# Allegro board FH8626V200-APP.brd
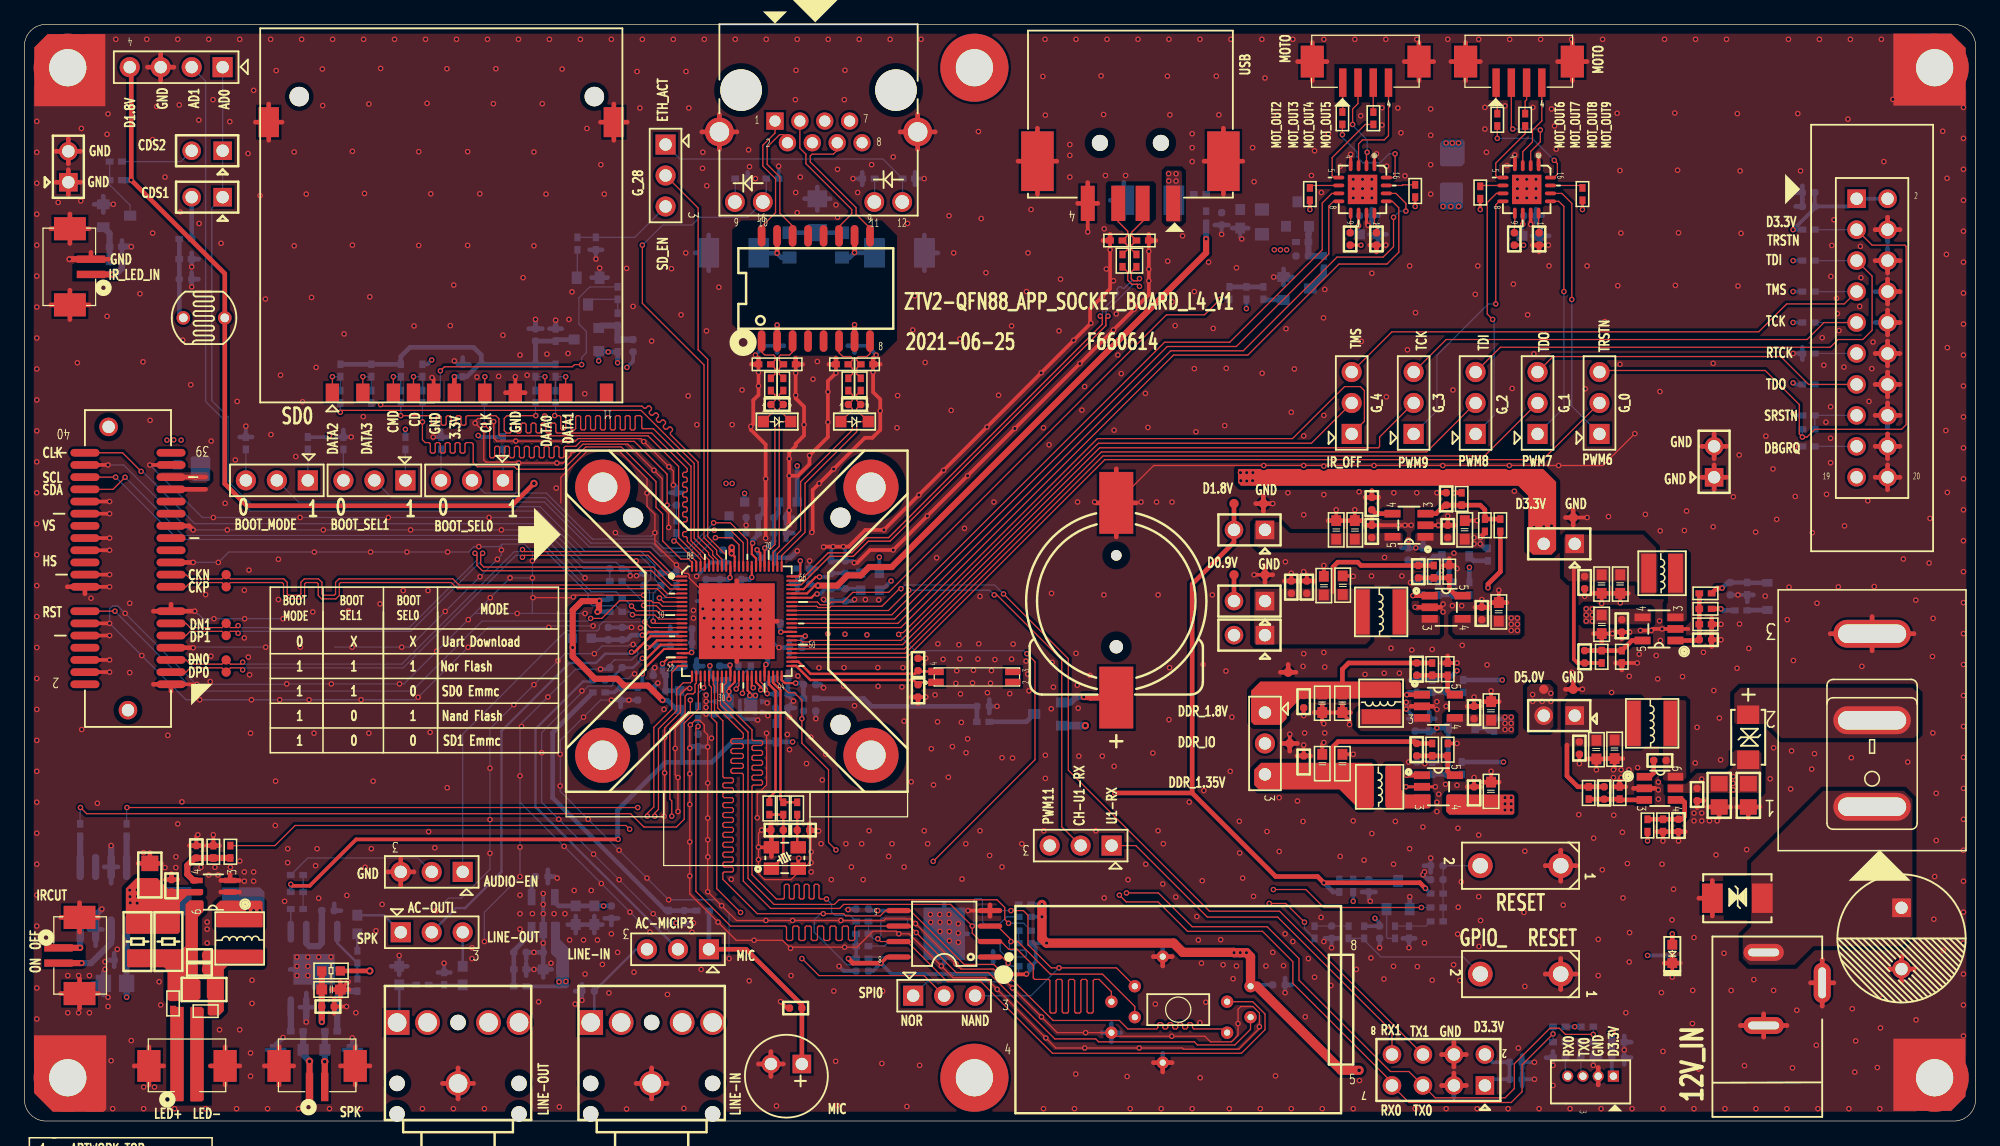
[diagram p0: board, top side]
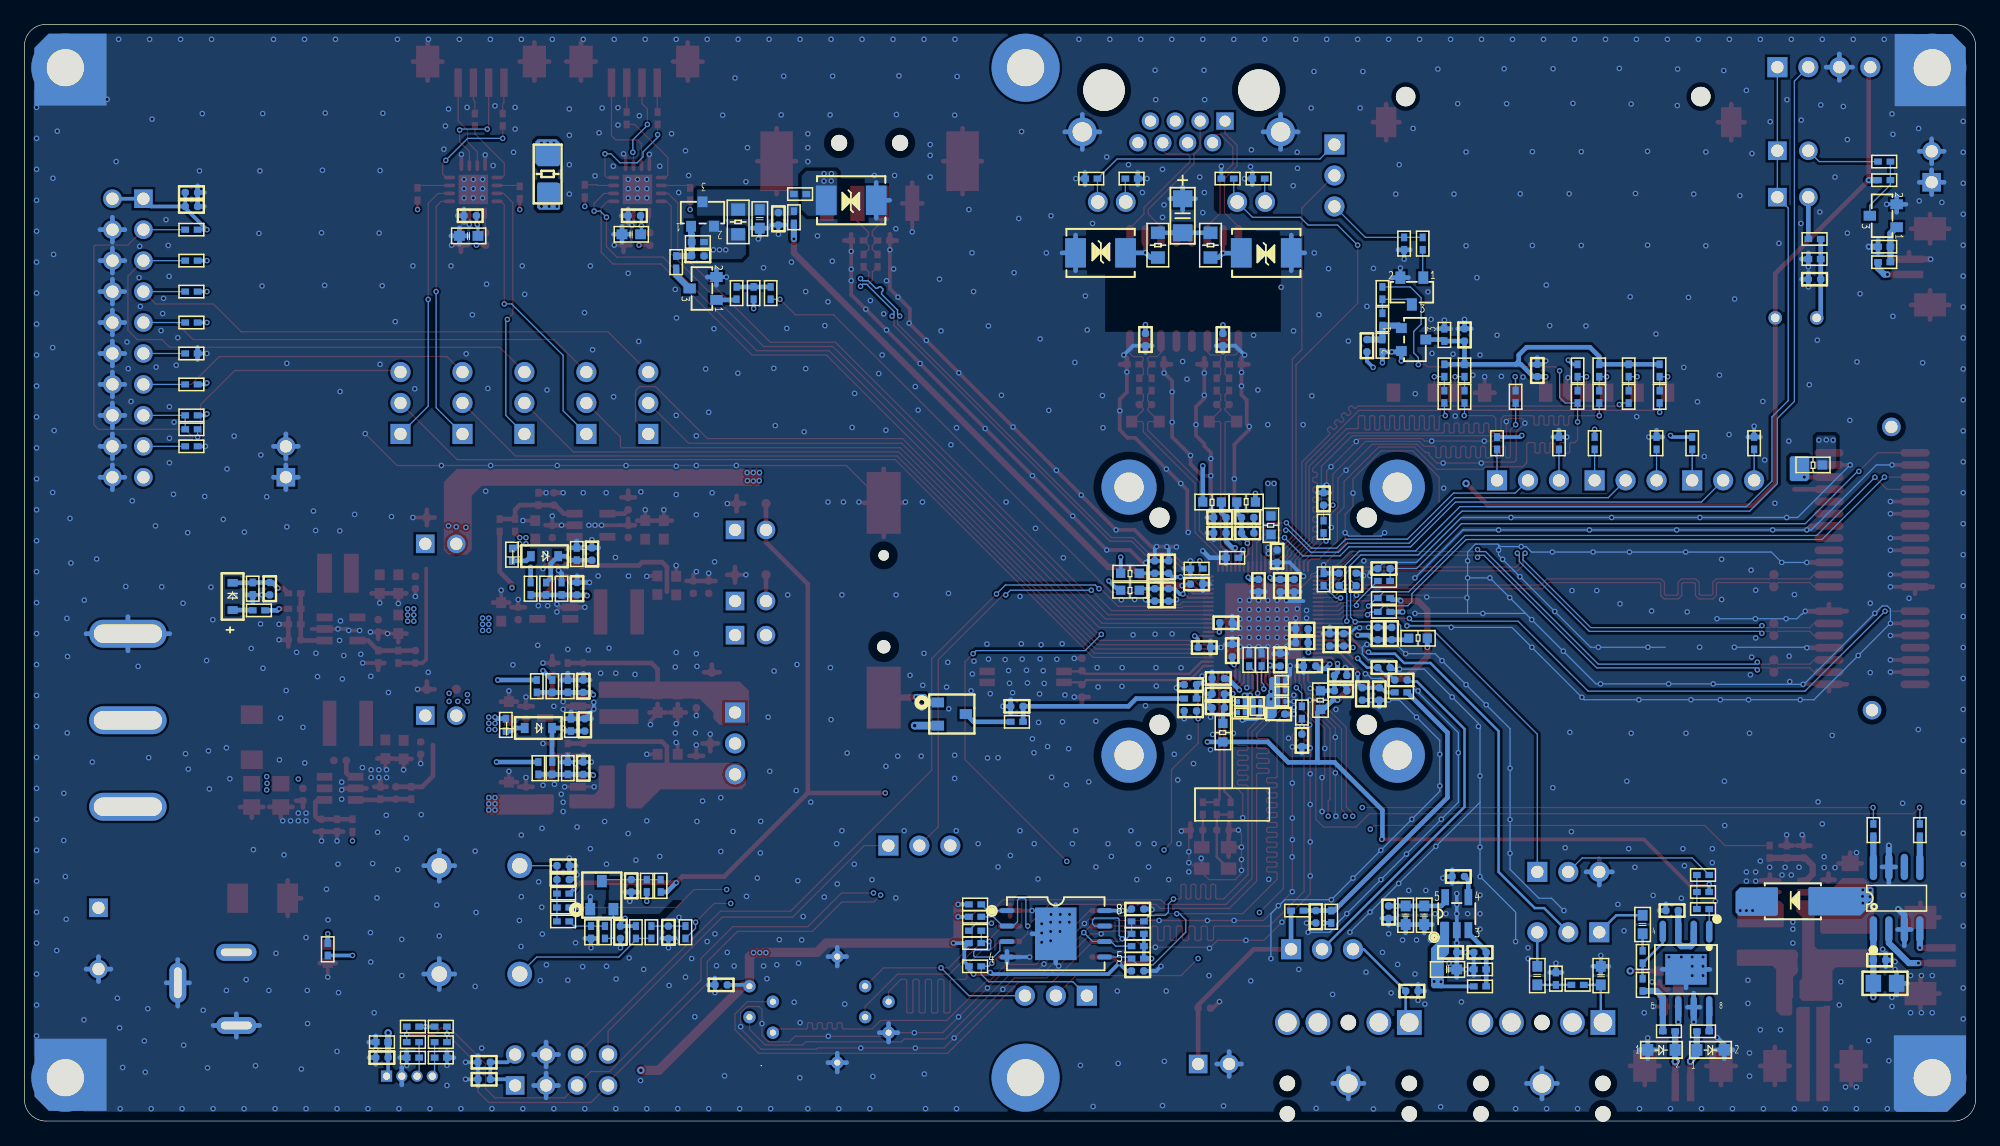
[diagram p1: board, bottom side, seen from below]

Outline 160 x 90 mm; copper layers: TOP, GND, VCC, BOTTOM. Coordinates in mm from the lower left corner of the outline.
Outline path: 0,88.22 arc(0.52,89.48) 1.78,90 158.22,90 arc(159.48,89.48) 160,88.22 160,1.78 arc(159.48,0.52) 158.22,0 1.78,0 arc(0.52,0.52) 0,1.78 0,88.22

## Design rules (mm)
net group ARM_JTAG_TRSTN: nets ARM_JTAG_TRSTN JTAG_SRSTN
net group CDS1: nets CDS1 N00509
net group CIS_CLK: nets CIS_CLK N16786493
net group DDR_D1.8V: nets DDR_D1.8V N15061
net group EN2: nets EN2 N11558
net group EN3: nets EN3 N17828
net group GPIO_RESET: nets GPIO_RESET N06017
net group IR_LED_IN: nets IR_LED_IN N12968
net group MOTO_OUT_2: nets MOTO_OUT_2 N16674187
net group MOTO_OUT_4: nets MOTO_OUT_4 N16674222
net group MOTO_OUT_6: nets MOTO_OUT_6 N16674257
net group MOTO_OUT_8: nets MOTO_OUT_8 N16674292
net group SPI1: nets NOR_CS SPI0_CSN_0
net group USB_PWREN: nets N08717 USB_PWREN
net group USBN: nets USB_DM USBN
net group USBP: nets USB_DP USBP
net group CDS2: nets CDS2 CIS_SCL CIS_SDA N07170 N13141 N16750268 N16750308 N16751673 N16786550 N16786676 N16794051 N16800878
net group CLK_IN: nets CLK_IN CLK_OUT N16795922 N16795926
net group EN1: nets EN1 N15235 N20335
net group EPHY_RXN: nets N16425817
net group EPHY_RXP: nets N16425841
net group EPHY_TXN: nets N16425857
net group EPHY_TXP: nets N16425869
net group HOLD: nets HOLD
net group LAN: nets EPHY_RXN EPHY_RXP EPHY_TXN EPHY_TXP PHY_RN PHY_RP PHY_TN PHY_TP
net group LDO_MICBIAS: nets LDO_MICBIAS N58665 N58697
net group N09603: nets N09603
net group N09903: nets N09903
net group N12324: nets N12328
net group RESETN: nets N06505 N06945 N06949 RESETN
net group RTC_VBAT: nets N16520538 N16795478 RTC_VBAT
net group SD0_3.3V: nets N00760 N00772 N00784 N00796 N00832 N00844 N08811 N09124 SD0_3.3V SD0_CD SD0_CMD SD0_DATA_0 SD0_DATA_1 SD0_DATA_2 SD0_DATA_3
net group SD0_CLK: nets N00808 N16609598 SD0_CLK
net group SPI: nets NAND_CS SPI0_D_2 SPI0_D_3
net group SPI0_CLK: nets N16589672
net group SPI0_D_2: nets WP
net group USB_VBUS: nets USB_VBUS
net group VM: nets N16569733 N16571270 VM

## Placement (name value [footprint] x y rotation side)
BT1  Battery  [BAT-22_8-10]  89.53 42.67 270 top
C1  100nF/10V  [C0402]  134.11 29.59 0 top
C2  100nF/25V  [C0402]  137.16 26.8 270 top
C3  470uF/35V  [DE10MM-H16]  153.92 14.99 270 top
C4  10uF/25V  [C0805]  141.36 26.73 270 top
C5  10uF/25V  [C0805]  138.97 26.73 270 top
C6  22uF/10V  [C0603]  128.91 30.48 270 top
C7  100nF/10V  [C0402]  127.51 30.61 270 top
C8  20pF/50V  [C0402]  129.54 26.92 270 top
C9  10uF/10V  [C0603]  130.4 30.51 270 top
C10  100nF/25V  [C0402]  135.64 24.26 90 top
C11  10uF/10V  [C0603]  129.34 40.77 90 top
C12  100nF/10V  [C0402]  130.99 40.64 90 top
C13  20pF/50V  [C0402]  127.94 38.1 90 top
C14  22uF/6.3V  [C0603]  129.34 44.07 270 top
C15  22uF/6.3V  [C0603]  130.86 44.07 270 top
C16  100nF/6.3V  [C0402]  127.94 44.2 270 top
C17  10uF/10V  [C0603]  118.11 48.51 270 top
C18  100nF/10V  [C0402]  116.71 48.39 270 top
C19  22uF/6.3V  [C0603]  107.57 48.51 90 top
C20  (*)  [C0402]  137.85 39.5 180 top
C21  22uF/6.3V  [C0603]  109.09 48.51 90 top
C22  100nF/6.3V  [C0402]  110.49 48.39 90 top
C23  (*)  [C0402]  116.59 51.05 270 top
C24  10nF/50V  [C0402]  110.49 50.67 90 top
C25  10uF/10V  [C0603]  120.27 33.66 270 top
C26  100nF/10V  [C0402]  118.87 33.53 270 top
C27  20pF/50V  [C0402]  114.17 37.08 270 top
C28  22uF/6.3V  [C0603]  108.08 34.29 270 top
C29  22uF/6.3V  [C0603]  106.43 34.29 270 top
C30  100nF/6.3V  [C0402]  104.9 34.42 270 top
C31  (*)  [C0402]  114.17 35.69 270 bottom
C32  100nF/10V  [C0402]  114.05 32.51 90 bottom
C33  100nF/10V  [C0402]  113.46 46.53 90 bottom
C34  10uF/10V  [C0603]  120.9 41.78 270 top
C35  100nF/10V  [C0402]  119.51 41.66 270 top
C36  20pF/50V  [C0402]  114.3 45.09 270 top
C37  22uF/6.3V  [C0603]  108.1 43.98 90 top
C38  22uF/6.3V  [C0603]  106.55 43.94 90 top
C39  10uF/6.3V  [C0402]  105.16 43.81 90 top
C40  100nF/6.3V  [C0402]  103.89 43.81 90 top
C41  100nF/10V  [C0402]  114.68 43.69 270 bottom
C42  10uF/6.3V  [C0402]  66.17 45.47 90 bottom
C43  100nF/6.3V  [C0402]  67.31 45.47 90 bottom
C44  100nF/6.3V  [C0402]  50.8 44.45 90 bottom
C45  10uF/6.3V  [C0402]  62.1 33.91 180 bottom
C46  10uF/6.3V  [C0402]  62.1 36.32 180 bottom
C47  100nF/6.3V  [C0402]  52.07 35.31 0 bottom
C48  10uF/6.3V  [C0402]  57.15 33.4 180 bottom
C49  10uF/6.3V  [C0402]  67.31 43.18 270 bottom
C50  100nF/6.3V  [C0402]  62.1 35.05 180 bottom
C51  100nF/6.3V  [C0402]  66.17 43.18 270 bottom
C52  15pF/50V  [C0402]  48.51 45.34 180 bottom
C53  10uF/6.3V  [C0402]  49.02 40.01 90 bottom
C54  100nF/6.3V  [C0402]  47.88 40.01 90 bottom
C55  5.6pF/50V  [C0402]  48.51 37.21 180 bottom
C56  1uF/6.3V  [C0402]  47.12 36.2 180 bottom
C57  100nF/6.3V  [C0201]  56.9 34.42 180 bottom
C58  100nF/6.3V  [C0201]  58.93 34.42 180 bottom
C59  1uF/25V  [C0402]  24.89 17.27 180 bottom
C60  100nF/6.3V  [C0402]  102.87 11.18 0 bottom
C61  100nF/6.3V  [C0402]  58.8 43.94 270 bottom
C62  100nF/10V  [C0402]  139.88 43.69 270 bottom
C63  10uF/6.3V  [C0402]  52.07 36.58 0 bottom
C64  10uF/10V  [C0603]  120.27 27.05 270 top
C65  100nF/10V  [C0402]  118.87 26.92 270 top
C66  20pF/50V  [C0402]  114.17 30.48 270 top
C67  22uF/6.3V  [C0603]  108.08 29.34 90 top
C68  22uF/6.3V  [C0603]  106.43 29.34 90 top
C69  100nF/6.3V  [C0402]  104.9 29.46 90 top
C70  (*)  [C0402]  114.17 28.96 270 bottom
C71  10uF/10V  [C0603]  25.15 10.79 180 top
C72  100nF/50V  [C0402]  24.89 9.4 180 top
C73  390nF/25V  [C0603]  27.3 16.13 270 bottom
C74  100nF/6.3V  [C0402]  51.82 39.5 90 bottom
C75  10uF/6.3V  [C0402]  52.96 39.5 90 bottom
C77  100nF/6.3V  [C0402]  64.39 35.81 180 bottom
C78  10pF/50V COG  [C0402]  61.72 23.88 0 top
C79  6.2pF/50V  [C0402]  73.28 35.31 90 top
C80  10pF/50V COG  [C0402]  63.88 23.88 180 top
C81  6.2pF/50V  [C0402]  73.28 37.47 270 top
C82  100nF/6.3V  [C0402]  57.28 46.35 90 bottom
C83  100nF/6.3V  [C0402]  54.61 37.34 180 bottom
C85  100nF/6.3V  [C0402]  63.25 38.86 0 bottom
C86  100nF/25V  [C0402]  14.35 13.59 0 top
C87  100nF/25V  [C0402]  14.1 22.1 90 top
C88  10uF/6.3V  [C0402]  55.24 39.24 0 bottom
C89  100nF/6.3V  [C0402]  55.24 40.39 0 bottom
C90  100nF/6.3V  [C0402]  57.02 43.94 270 bottom
C91  100nF/6.3V  [C0402]  60.96 38.61 90 bottom
C92  100nF/6.3V  [C0402]  61.47 40.89 180 bottom
C93  100nF/6.3V  [C0402]  55.88 43.94 270 bottom
C94  22uF/25V  [C0805]  14.73 10.79 0 top
C95  2.2uF/50V  [C0402]  14.35 12.45 0 top
C96  100nF/6.3V  [C0402]  49.91 63.63 90 bottom
C97  100nF/6.3V  [C0402]  52.2 44.45 90 bottom
C98  100nF/6.3V  [C0201]  58.93 33.66 180 bottom
C99  1uF/10V  [C0402]  104.78 70.99 0 bottom
C100  100nF/6.3V  [C0402]  68.71 12.32 0 bottom
C101  100nF/6.3V  [C0402]  68.71 17.4 180 bottom
C102  100nF/6.3V  [C0402]  78.61 34.04 0 bottom
C103  100nF/6.3V  [C0402]  35.94 61.59 90 bottom
C104  100nF/6.3V  [C0402]  41.91 64.52 90 bottom
C105  10uF/25V  [C0805]  10.29 20.19 90 top
C106  100nF/25V  [C0402]  12.06 19.3 90 top
C107  22uF/10V  [C0603]  43.31 12.45 0 bottom
C108  5.6pF/50V  [C0402]  63.25 9.27 180 top
C109  100nF/10V  [C0402]  43.05 13.84 0 bottom
C110  22uF/6.3V  [C0603]  45.21 16.89 270 bottom
C111  22uF/6.3V  [C0603]  46.74 16.89 270 bottom
C112  100nF/6.3V  [C0402]  48.13 17.14 270 bottom
C113  4.7uF/6.3V  [C0402]  54.1 16.76 270 bottom
C114  4.7uF/6.3V  [C0402]  50.29 35.05 270 bottom
C115  10nF/50V  [C0402]  42.42 20.07 0 bottom
C116  100nF/6.3V  [C0201]  56.9 35.31 180 bottom
C117  100nF/6.3V  [C0201]  56.9 36.2 180 bottom
C118  100nF/10V  [C0402]  40.64 13.84 180 bottom
C119  5.6pF/50V  [C0402]  46.23 10.67 180 bottom
C120  100nF/6.3V  [C0201]  60.2 34.42 0 bottom
C121  100nF/6.3V  [C0201]  60.2 33.53 0 bottom
C122  10uF/6.3V  [C0402]  61.98 48.26 0 bottom
C123  100nF/6.3V  [C0402]  61.98 49.53 0 bottom
C124  10uF/6.3V  [C0402]  59.69 49.53 180 bottom
C125  100nF/6.3V  [C0402]  59.69 48.26 180 bottom
C135  100nF/50V  [C0402]  48.9 35.05 270 bottom
C146  2.2uF/6.3V  [C0603]  35.94 11.94 270 bottom
C147  82nF/50V  [C0603]  30.73 11.94 90 bottom
C148  100nF/6.3V  [C0402]  130.68 5.21 0 bottom
C149  100nF/6.3V  [C0402]  13.21 69.09 0 bottom
C150  100nF/6.3V  [C0402]  146.3 75.06 0 bottom
C151  100nF/6.3V  [C0402]  146.3 76.2 180 bottom
C152  10uF/25V  [C0805]  7.43 11.3 180 bottom
C153  100nF/25V  [C0402]  7.87 13.21 180 bottom
C154  10pF/50V  [C0402]  61.72 58.8 0 top
C155  10pF/50V  [C0402]  68.07 58.8 0 top
C158  100nF/10V  [C0402]  98.17 74.04 270 bottom
C159  10uF/10V  [C0603]  99.69 74.04 270 bottom
C160  100nF/6.3V  [C0402]  111.12 15.49 270 bottom
C161  100nF/6.3V  [C0402]  107.19 15.49 270 bottom
C162  100nF/6.3V  [C0402]  110.24 19.3 270 bottom
C163  (*)  [C0402]  115.82 20.95 180 bottom
C164  100nF/6.3V  [C0402]  115.82 19.81 180 bottom
C165  100nF/25V  [C0402]  61.72 64.14 270 bottom
C166  1nF/2000V  [C1206]  65.02 74.3 270 bottom
C167  100nF/25V  [C0402]  68.07 64.14 270 bottom
C177  15pF/50V  [C0402]  55.24 31.24 270 bottom
C178  15pF/50V  [C0402]  53.47 51.05 90 bottom
C181  10uF/10V  [C0603]  123.57 72.64 180 bottom
C182  100nF/10V  [C0402]  122.17 72.39 270 top
C183  100nF/10V  [C0402]  123.44 74.3 180 bottom
C184  100nF/10V  [C0402]  109.98 74.3 180 bottom
C185  10uF/10V  [C0603]  110.24 72.77 180 bottom
C186  2.2uF/50V  [C0402]  110.87 72.39 270 top
C187  100nF/10V  [C0402]  108.71 72.39 270 top
C188  2.2uF/50V  [C0402]  124.21 72.39 270 top
C190  4.7uF/6.3V  [C0402]  64.39 33.66 180 bottom
C191  10uF/6.3V  [C0402]  57.02 37.85 90 bottom
C194  100nF/6.3V  [C0402]  122.3 3.43 0 bottom
C195  100nF/6.3V  [C0402]  122.3 4.83 180 bottom
C196  100nF/6.3V  [C0402]  63.88 44.07 0 bottom
CN1  Audio  [PHONE_JACK]  51.44 5.59 180 top
CN5  Audio  [PHONE_JACK]  35.56 5.59 180 top
D1  B250A-13F  [DO-214AC]  141.35 31.5 270 top
D2  SMBJ15CA  [DO-214AA]  140.46 18.29 0 top
D3  LED GREEN  [LED0603]  135.13 13.72 270 top
D4  IN4148WS  [SOD-323]  117.86 32.26 0 bottom
D5  IN4148WS  [SOD-323]  117.35 46.35 0 bottom
D6  LBAT54CLT1G  [SOT23]  83.95 33.4 270 bottom
D7  PESD5V0L1BA  [SOD323]  21.74 5.84 180 bottom
D8  ESD5431N  [D0402]  130.68 6.48 0 bottom
D9  ESD5431N  [D0402]  125.86 5.21 0 bottom
D10  ESD5431N  [D0402]  128.14 5.21 180 bottom
D11  IN4148WS  [SOD-323]  142.93 43.05 270 bottom
D12  GL5537-1  [RGL55]  14.73 65.91 180 top
D13  ESD73011N  [D0402]  91.69 72.26 0 top
D14  ESD73011N  [D0402]  89.53 72.26 0 top
D15  4532-470V/P3100SC  [DO-214AA]  58.17 71.25 0 bottom
D16  4532-470V/P3100SC  [DO-214AA]  71.75 71.25 180 bottom
D17  SMBJ15CA  [DO-214AA]  92.2 75.56 0 bottom
D18  PGB1010402NR  [D0402]  60.71 62.1 180 top
D19  ESD5431N  [D0402]  72.52 77.34 180 bottom
D20  UDD32C03L01  [SOD323]  61.72 57.4 0 top
D21  PGB1010402NR  [D0402]  62.74 62.1 0 top
D22  PGB1010402NR  [D0402]  67.06 62.1 180 top
D23  ESD5431N  [D0402]  61.34 77.34 180 bottom
D24  PGB1010402NR  [D0402]  69.09 62.1 0 top
D25  PESD5V0L1BA  [SOD323]  25.76 5.84 180 bottom
D26  IN5819  [DO-214AC-IN5819]  14.99 18.03 180 bottom
D32  UDD32C03L01  [SOD323]  68.07 57.4 0 top
J1  DC005-2.0MM  [DC-3]  142.62 13.84 0 top
J2  MR1-110-C5N-BB  [PS_3PIN-7MM]  151.51 32.89 180 top
J3  MEC1-120-02-F-D-LC  [HEADER20X2_1MM_SMD]  8.49 45.34 180 top
J4  SD Card  [PROCONN_SD]  46.74 84.07 180 top
J5  1.25T-2-2A  [HEADER2_125MM_SMD]  24 2.41 0 top
J6  GMI6027P-2C44DB  [GMI6027P-2C]  62.48 3.68 180 top
J7  1.25T-2-2A  [HEADER2_125MM_SMD]  13.34 2.41 0 top
J12  1.25T-4PL  [HEADER4_125MM]  130.3 3.68 270 top
J13  1.25T-2-2A  [HEADER2_125MM_SMD]  5.84 70.1 90 top
J14  CON4-254MM  [SIP4_254MM]  16.26 86.49 180 top
J15  1.25T-2-2A  [HEADER2_125MM_SMD]  2.41 13.59 270 top
J17  RJ45-B-1*1  [RJ45_LED-1]  61.55 82.07 0 top
J19  1.25T-2-4A  [HEADER4_125MM_SMD]  109.98 84.84 0 top
J20  1.25T-2-4A  [HEADER4_125MM_SMD]  122.56 84.84 0 top
J21  USB-A  [USBX1_SMD]  91.69 75.31 180 top
JP1  2.54MM Needle  [SIP3_254MM]  23.24 52.58 180 top
JP2  2.54MM Needle  [SIP3_254MM]  31.24 52.58 180 top
JP3  2.54MM Needle  [SIP3_254MM]  39.24 52.58 180 top
JP4  2.54MM Needle  [SIP3_254MM]  52.58 80.14 270 top
JP5  2.54MM Needle  [SIP2_254MM]  138.56 52.83 90 top
JP6  2.54MM Needle  [SIP2_254MM]  3.6 77.05 90 top
JP7  2.54MM Needle  [SIP3_254MM]  119 56.39 90 top
JP8  2.54MM Needle  [SIP2_254MM]  127.13 33.27 180 top
JP9  2.54MM Needle  [SIP3_254MM]  113.92 56.39 90 top
JP10  2.54MM Needle  [SIP3_254MM]  108.84 56.39 90 top
JP11  2.54MM Needle  [SIP3_254MM]  129.16 56.39 90 top
JP12  2.54MM Needle  [SIP3_254MM]  124.08 56.39 90 top
JP13  2.54MM Needle  [SIP2_254MM]  127.13 47.37 180 top
JP14  2.54MM Needle  [SIP3_254MM]  72.88 10.29 0 top
JP15  2.54MM Needle  [SIP2_254MM]  101.73 39.88 180 top
JP16  2.54MM Needle  [SIP2_254MM]  101.73 42.67 180 top
JP17  2.54MM Needle  [SIP3_254MM]  56.13 14.1 180 top
JP18  2.54MM Needle  [SIP2_254MM]  101.73 48.51 180 top
JP19  2.54MM Needle  [SIP3_254MM]  101.73 33.53 270 top
JP20  2.54MM Needle  [SIP3_254MM]  35.94 20.45 180 top
JP22  2.54MM Needle  [SIP3_254MM]  89.15 22.61 180 top
JP23  2.54MM Needle  [SIP3_254MM]  30.86 15.49 0 top
JP29  2.54MM Needle  [SIP2_254MM]  16.26 75.82 180 top
JP30  2.54MM Needle  [SIP2_254MM]  16.26 79.63 180 top
L1  WPN4020H4R7MT  [L4X4H3]  133.48 32.64 180 top
L2  SWPA3015S4R7MT  [L3X3H15]  134.29 44.96 180 top
L3  SWPA3015S4R7MT  [L3X3H15]  111.25 34.29 90 top
L4  WPN4020H2R2MT  [L4X4H3]  111.25 41.78 180 top
L5  SWPA3015S4R7MT  [L3X3H15]  111.12 27.43 180 top
L6  SWPA4026S100MT  [L4X4H3]  17.65 14.99 270 top
MQ1  AF2301P  [SOT_23]  45.09 64.14 90 bottom
MQ3  AF2301P  [SOT_23]  104.39 75.44 0 bottom
NOREF  -  []  0 0 90 top
NOREF#2  -  []  0 91.82 0 top
Q1  MMB3904  [SOT23_2]  46.23 68.07 180 bottom
Q3  MMB3904  [SOT23_2]  7.62 74.3 270 bottom
Q4  MMB3904  [SOT23_2]  104.39 68.33 270 bottom
R1  10K 5%  [R0402]  135.13 14.1 270 bottom
R2  47K 5%  [R0402]  133.1 24.26 90 top
R3  100K 1%  [R0402]  128.27 26.92 90 top
R4  10K 5%  [R0402]  134.37 24.26 90 top
R5  13.7K 1%  [R0402]  130.81 26.92 270 top
R6  100K 1%  [R0402]  129.34 38.1 270 top
R7  (*)  [R0402]  137.85 42.04 180 top
R8  (*)  [R0402]  137.85 40.77 180 top
R9  22.1K 1%  [R0402]  130.99 38.1 90 top
R10  (*)  [R0402]  119.76 48.9 90 top
R11  (*)  [R0402]  117.86 51.05 270 top
R12  0R 5%  [R0402]  137.85 43.31 180 top
R13  0R 5%  [R0402]  121.03 48.9 90 top
R14  150K 1%  [R0402]  115.44 37.08 90 top
R15  (*)  [R0402]  117.98 35.69 270 bottom
R16  75K 1%  [R0402]  116.71 37.08 270 top
R17  (*)  [R0402]  115.44 35.69 270 bottom
R18  43K 5%  [R0402]  120.52 32.51 270 bottom
R19  120K 1%  [R0402]  115.19 32.51 90 bottom
R20  0R 5%  [R0402]  116.71 35.69 270 bottom
R21  100K 1%  [R0402]  120.02 46.48 270 bottom
R22  75K 1%  [R0402]  114.71 46.53 90 bottom
R23  59K 1%  [R0402]  115.57 45.09 90 top
R24  (*)  [R0402]  118.49 43.69 270 bottom
R25  (*)  [R0402]  115.95 43.69 270 bottom
R26  110K 1%  [R0402]  116.84 45.09 270 top
R27  10K 5%  [R0402]  117.22 43.69 270 bottom
R28  0R 5%  [R0603]  69.34 44.96 0 bottom
R29  0R 5%  [R0603]  61.72 31.88 90 bottom
R30  0R 5%  [R0603]  69.34 43.56 0 bottom
R31  200R 1%  [R0402]  63.88 45.34 0 bottom
R32  0R 5%  [R0603]  45.72 39.62 180 bottom
R33  22R 5%  [R0402]  48.51 44.32 0 bottom
R34  2.2K 5%  [R0402]  48.51 41.78 0 bottom
R35  2.2K 5%  [R0402]  48.51 42.93 0 bottom
R36  0R 5%  [R0603]  53.72 34.54 90 bottom
R37  0R 5%  [R0402]  64.39 34.67 180 bottom
R38  4.02K 1%  [R0402]  53.47 44.45 270 bottom
R39  0R 5%  [R0402]  61.09 25.65 90 top
R40  1M 5%  [R0402]  62.23 25.65 270 top
R41  22R 5%  [R0402]  63.37 25.65 90 top
R42  10K 5%  [R0402]  23.24 55.63 90 bottom
R43  10K 5%  [R0402]  18.16 55.63 90 bottom
R44  82K 1%  [R0402]  140.77 41.91 0 bottom
R45  10K 5%  [R0402]  31.24 55.63 90 bottom
R46  10K 5%  [R0402]  26.16 55.63 90 bottom
R47  10K 5%  [R0402]  39.24 55.63 90 bottom
R48  10K 5%  [R0402]  34.16 55.63 90 bottom
R49  6.04K 1%  [R0402]  60.96 46.23 0 bottom
R50  0R 5%  [R0603]  13.34 53.85 0 bottom
R51  0R 5%  [R0402]  82.04 15.62 180 bottom
R52  10K 5%  [R0402]  82.04 12.7 180 bottom
R53  10K 5%  [R0402]  82.04 16.76 180 bottom
R54  10K 5%  [R0402]  68.71 15.37 180 bottom
R55  10K 5%  [R0402]  82.04 14.61 180 bottom
R56  10K 5%  [R0402]  68.71 14.35 180 bottom
R57  10K 5%  [R0402]  68.71 13.34 180 bottom
R58  0R 5%  [R0402]  68.71 16.38 180 bottom
R59  10K 5%  [R0402]  82.04 17.78 180 bottom
R60  10K 5%  [R0402]  22.35 18.8 180 bottom
R61  1K 5%  [R0402]  78.61 32.77 0 bottom
R62  0R 5%  [R0402]  22.35 20.19 0 bottom
R63  10K 5%  [R0402]  22.35 17.4 180 bottom
R64  10K 5%  [R0402]  28.45 61.59 270 bottom
R65  10K 5%  [R0402]  25.91 61.59 270 bottom
R66  10K 5%  [R0402]  43.56 61.59 270 bottom
R67  10K 5%  [R0402]  41.91 61.59 270 bottom
R68  22R 5%  [R0402]  41.91 59.44 90 bottom
R69  22R 5%  [R0402]  43.56 59.44 90 bottom
R70  22R 5%  [R0402]  25.91 59.44 90 bottom
R71  22R 5%  [R0402]  28.45 59.44 90 bottom
R72  0R 5%  [R0402]  37.72 59.44 90 bottom
R73  100K 5%  [R0402]  48.64 63.63 270 bottom
R74  100K 5%  [R0402]  43.56 64.52 270 bottom
R75  0R 5%  [R0402]  48.64 67.94 270 bottom
R76  10K 5%  [R0402]  48.64 65.79 270 bottom
R77  22R 5%  [R0402]  32.64 59.44 90 bottom
R78  1K 5%  [R0402]  45.34 72.01 270 bottom
R79  22R 5%  [R0402]  30.86 59.44 90 bottom
R80  4.7K 5%  [R0402]  46.86 72.01 270 bottom
R81  10K 5%  [R0402]  32.64 61.59 270 bottom
R82  10K 5%  [R0402]  30.86 61.59 270 bottom
R83  0R 5%  [R0603]  57.78 48.9 90 bottom
R84  75K 1%  [R0402]  141.28 43.69 270 bottom
R85  150K 1%  [R0402]  115.44 30.48 90 top
R86  (*)  [R0402]  117.86 28.96 270 bottom
R87  (*)  [R0402]  115.44 28.96 270 bottom
R88  120K 1%  [R0402]  116.71 30.48 270 top
R89  0R 5%  [R0402]  116.71 28.96 270 bottom
R90  0R 5%  [R0402]  22.35 7.37 0 bottom
R91  0R 5%  [R0603]  25.15 12.32 0 top
R92  75R 1%  [R0805]  62.74 71.88 270 bottom
R93  20K 1%  [R0402]  27.3 13.46 270 bottom
R94  0R 5%  [R0402]  25.15 7.37 180 bottom
R95  75R 1%  [R0805]  67.06 71.88 270 bottom
R96  0R 5%  [R0603]  62.61 50.8 0 bottom
R97  0R 5%  [R0603]  59.82 50.8 180 bottom
R98  100K 1%  [R0402]  27.3 11.18 270 bottom
R99  0R 5%  [R0402]  12.19 9.65 270 top
R101  10K 5%  [R0402]  106.55 70.48 90 bottom
R102  1K 5%  [R0402]  55.63 17.27 180 bottom
R103  (*1K 5%)  [R0402]  52.83 16.76 270 bottom
R104  10K 5%  [R0402]  15.49 22.1 90 top
R105  10K 5%  [R0402]  40.64 11.05 180 bottom
R106  10K 5%  [R0402]  40.64 12.45 180 bottom
R107  1K 5%  [R0402]  47.12 35.18 0 bottom
R108  1K 5%  [R0402]  16.89 22.1 270 top
R109  0.25R 1%  [R1206]  9.27 14.73 270 top
R110  0.25R 1%  [R1206]  11.81 14.73 270 top
R111  0R 5%  [R0402]  14.86 9.02 180 top
R122  10K 5%  [R0402]  125.86 7.75 0 bottom
R124  10K 5%  [R0402]  128.14 7.75 180 bottom
R125  100R 5%  [R0402]  128.14 6.48 180 bottom
R127  100R 5%  [R0402]  125.86 6.48 0 bottom
R129  100R 5%  [R0402]  13.21 72.39 0 bottom
R130  0R 5%  [R0402]  7.49 78.74 180 bottom
R131  10K 5%  [R0402]  7.49 77.22 0 bottom
R132  100K 1%  [R0402]  13.21 70.74 180 bottom
R133  1K 5%  [R0402]  7.49 70.48 0 bottom
R134  47K 5%  [R0402]  7.49 71.75 0 bottom
R135  10K 5%  [R0402]  146.3 73.15 180 bottom
R136  4.7K 5%  [R0402]  146.3 70.61 180 bottom
R137  4.7K 5%  [R0402]  146.3 68.07 180 bottom
R138  4.7K 5%  [R0402]  146.3 65.53 180 bottom
R139  4.7K 5%  [R0402]  146.3 62.99 180 bottom
R140  (*)  [R0402]  146.3 60.45 180 bottom
R141  (*)  [R0402]  146.3 57.91 180 bottom
R142  4.7K 5%  [R0402]  146.3 55.37 180 bottom
R143  22R 5%  [R0402]  146.3 56.77 0 bottom
R144  1K 5%  [R0402]  8.38 23.88 90 bottom
R145  1K 5%  [R0402]  4.57 23.88 90 bottom
R146  0R 5%  [R0402]  91.19 70.61 90 top
R147  0R 5%  [R0402]  90.04 70.61 90 top
R150  0R 5%  [R0402]  108.08 82.3 90 top
R151  0R 5%  [R0402]  110.62 82.3 90 top
R152  0R 5%  [R0402]  120.78 82.17 90 top
R153  0R 5%  [R0402]  123.06 82.17 90 top
R157  (*)  [R0805]  101.47 73.79 90 bottom
R158  0R 5%  [R0402]  96.9 74.17 270 bottom
R159  100K 5%  [R0402]  104.78 72.14 180 bottom
R160  0R 5%  [R0402]  96.39 76.07 180 bottom
R161  10K 5%  [R0402]  100.2 67.94 270 bottom
R162  0R 5%  [R0402]  98.81 67.94 90 bottom
R163  10K 5%  [R0402]  101.6 67.94 270 bottom
R164  10K 5%  [R0402]  109.86 15.49 270 bottom
R165  1K 5%  [R0402]  108.58 15.49 90 bottom
R166  0R 5%  [R0402]  105.79 15.49 270 bottom
R167  0R 5%  [R0402]  108.97 19.3 90 bottom
R168  (*)  [R0402]  115.82 18.67 180 bottom
R169  (*)  [R0402]  107.82 19.3 90 bottom
R170  1K 5%  [R0402]  112.39 15.49 90 bottom
R171  0R 5%  [R0402]  115.82 16.38 0 bottom
R172  0R 5%  [R0402]  115.82 17.53 180 bottom
R173  1.2K 5%  [R0402]  113.54 15.49 90 bottom
R174  10R 1%  [R0402]  61.21 60.45 270 top
R176  510R 5%  [R0402]  69.22 77.34 0 bottom
R177  10R 1%  [R0402]  62.23 60.45 270 top
R178  10R 1%  [R0402]  67.56 60.45 270 top
R179  510R 5%  [R0402]  58.8 77.34 180 bottom
R181  10R 1%  [R0402]  68.58 60.45 270 top
R203  22R 5%  [R0402]  55.24 33.53 90 bottom
R204  22R 5%  [R0402]  53.47 48.77 270 bottom
R207  10K 5%  [R0402]  127.76 76.07 90 top
R208  (*)  [R0402]  119.38 76.2 90 top
R209  (*)  [R0402]  105.41 76.07 90 top
R210  0R 5%  [R1206]  117.09 77.72 270 bottom
R211  10K 5%  [R0402]  114.05 76.33 90 top
RF1  470R 5%  [R0402]  32.64 11.18 180 bottom
RF2  10K 5%  [R0402]  34.42 11.68 270 bottom
RR2  240R 1%  [R0402]  59.56 37.85 270 bottom
RR3  240R 1%  [R0402]  58.55 37.85 270 bottom
S1  1TS002A-2300-5000  [KEY_2PIN]  122.68 12.06 270 top
S2  1TS002A-2300-5000  [KEY_2PIN]  122.68 20.95 270 top
T1  -  [TP30]  124.59 35.43 270 top
T2  -  [TP30]  127 35.43 270 top
T3  -  [TP30]  124.59 49.53 180 top
T4  -  [TP30]  99.19 50.67 90 top
T5  -  [TP30]  127 49.53 180 top
T6  -  [TP30]  101.6 50.67 90 top
T7  -  [TP30]  103.63 34.8 0 top
T8  -  [TP30]  103.63 36.83 0 top
T9  -  [TP30]  99.19 44.83 90 top
T10  -  [TP30]  101.73 44.83 90 top
T11  Mark Point  [C220D120]  3.56 86.44 0 top
T12  Mark Point  [C220D120]  77.9 86.44 0 top
T13  Mark Point  [C220D120]  156.64 86.44 0 top
T14  Mark Point  [C220D120]  3.56 3.56 0 top
T15  Mark Point  [C220D120]  156.64 3.56 0 top
T16  Mark Point  [C220D120]  77.9 3.56 0 top
T17  -  [TP30]  103.63 28.45 270 top
T18  -  [TP30]  103.76 30.99 270 top
T19  -  [TP30]  16.55 36.84 90 top
T20  -  [TP30]  16.55 37.84 90 top
T21  -  [TP30]  16.55 39.84 90 top
T22  -  [TP30]  16.55 40.84 90 top
T23  -  [TP30]  16.55 43.84 90 top
T24  -  [TP30]  16.55 44.84 90 top
U1  SY8120B  [SOT23_6]  134.11 27.3 270 top
U2  SY8088AAC  [SOT23_5]  134.04 40.39 90 top
U3  TPS79318DBVR  [SOT23_5]  113.54 48.9 90 top
U4  SY8088AAC  [SOT23_5]  115.95 34.04 270 top
U5  SY8089AAC  [SOT23_5]  116.59 42.16 270 top
U6  Nand Flash Socket  [SOP8_SPI_SOCKET-267X17]  94.61 9.14 0 top
U7  SX32Y024000B91T-U_24MHz 9PF 10ppm  [CRSTALY_3225]  62.36 21.59 0 top
U8  Q13MC1461000600/32.768kHz  [MC-146]  78.11 36.45 0 top
U9  GD25Q127CSIG/W25Q128JVSIQ  [SO8_200MIL]  75.43 15.37 180 top
U10  GD5F1GQ4UCYIG/W25N01GVZEIG  [SOP8-NANDFLASH]  75.43 15.37 180 bottom
U11  TPS79318DBVR  [SOT23_5]  42.55 17.02 180 bottom
U12  SY8088AAC  [SOT23_5]  115.95 27.43 270 top
U13  SGM4871YPS8/TR  [SOIC8-SGM4871]  23.75 12.45 270 bottom
U14  FH8852v101  [QFN88_HL_SOCKET]  58.42 41.02 0 top
U15  CON2x4-254MM  [DIP4X2_254MM]  119.76 2.92 180 top
U16  SY8703  [TSOT23-6]  15.49 18.8 90 top
U18  CON2x10-254MM  [DIP10X2_254MM]  150.24 75.69 0 top
U19  AZ6208BM  [SOP8_127-620X500]  6.48 18.29 90 bottom
U22  MAX809SN160T1/SGM809-RXN3L/TR  [SOT23]  112.65 18.54 180 bottom
U23  H1102NLT  [SOP16_270_50]  64.9 68.33 0 top
U26  HR8833SQ  [QFN16_HR8833]  109.73 76.45 270 top
U27  HR8833SQ  [QFN16_HR8833]  123.19 76.45 270 top

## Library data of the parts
BT1 = BATTERY_0: User Part Number: HAMP; Tolerance: #TOL
C1 C2 C7 C8 C10 C13 C16 C18 C20 C23 C39-C44 = CAP0402: signal model: DEFAULT_CAPACITOR_100000pF_2_1
C3 = ECAP-DIP: signal model: DEFAULT_CAPACITOR_100000pF_2_1
C4 = CAP0805: signal model: DEFAULT_CAPACITOR_100000pF_2_1
C5 = CAP0805: signal model: DEFAULT_CAPACITOR_1000pF_2_1
C6 C11 C17 = CAP0603: signal model: DEFAULT_CAPACITOR_1000pF_2_1
C9 = CAP0603: signal model: DEFAULT_CAPACITOR_1e+006pF_2_1
C12 = CAP0402: signal model: DEFAULT_CAPACITOR_1000pF_2_1
C14 C15 C19 C25 C28 C29 C34 C37 C38 C64 C67 C68 C71 C73 C107 C110 C111 C146 C147 C159 C181 C185 = CAP0603
C21 = CAP0603: signal model: DEFAULT_CAPACITOR_100000pF_2_1
C22 C26 C27 C30-C33 C35 C36 C46-C56 C59-C63 C65 C66 C69 C70 C72 C74 C75 C77-C83 C85-C93 C95-C97 C99-C104 C106 C108 C109 C112-C115 C118 C119 C122-C125 C135 C148-C151 C153-C155 C158 C160-C165 C167 C177 C178 C182-C184 C186-C188 C190 C191 C194-C196 = CAP0402
C24 C45 = CAP0402: signal model: DEFAULT_CAPACITOR_1e+006pF_2_1
C57 C58 C98 C116 C117 C120 C121 = CAP0201: Tolerance: TOLERANCE; User Part Number: USERPART#
C94 C105 C152 = CAP0805
C166 = CAP1206
CN1 CN5 = PHONE
D1 D4 D5 D11 = DIODE
D2 D7-D10 D13-D25 D32 = TVS
D3 = LED0603
D6 = SBD
D12 = LED
D26 = Diode
J1 = DC JACK: User Part Number: HAMP; Tolerance: #TOL
J2 = POWER SWITCH
J3 = MEC1-120-02-F-D-LC: signal model: MAC_MAC
J4 = SD: signal model: SIP4X1_S1X4_254MM
J5 J7 J13 J15 = CONNECT2_125MM
J6 = MIC IN
J12 = CONNECT4_125MM_DIP
J14 = CON4-254MM
J17 = RJ45_LED
J19 J20 = CONNECT4_125MM
J21 = USB-A
JP1-JP4 JP7 JP9-JP12 JP14 JP17 JP19 JP20 JP22 JP23 = JUMP SWITCH
JP5 JP6 JP8 JP13 JP15 JP16 JP18 JP29 JP30 = JUMP
L1-L5 = INDUCTOR
L6 = Inductor
MQ1 MQ3 = AF2301P
Q1 Q3 Q4 = NPN
R1-R3 R19 R21 R23 R38 R42 R44 R45 R54 R55 R73 R74 R78 R80 R81 R84-R90 R93 R94 R98 R99 R101 R104 R105 R107 R108 R111 R122 R124 R125 R127 R132 R134-R139 R142 R144 R145 R159 R163-R165 R168 R176 R179 R207 R211 RF1 RF2 RR2 RR3 = RES0402
R4-R15 R17 R20 R24 R25 R37 R39 R51 R58 R72 R75 R103 R130 R140 R141 R146 R147 R150-R153 R158 R160 R162 R166 R167 R169-R173 R208 R209 = RES0402: signal model: R0603-__0R_1_R0402_22R_22R
R16 R18 R22 R26 R27 R47 R161 = RES0402: signal model: R0603
R28 = RES0603: signal model: R0603
R29 R30 = RES0603: signal model: DEFAULT-sd
R31 = RES0402: signal model: DEFAULT_RESISTOR_47000OHM_2_1
R32 = RES0603: signal model: DEFAULT_RESISTOR_47000OHM_2_1
R33 R41 R68-R71 R77 R79 R143 R203 R204 = RES0402: signal model: DEFAULT
R34 R35 R43 R46 R59-R64 R67 R106 = RES0402: signal model: DEFAULT-sd
R36 = RES0603: signal model: DEFAUL
R40 R48 R49 R52 R76 R102 R129 R131 R133 = RES0402: signal model: RES_R0402_22R_22R
R50 = RES0603: signal model: RES_R0402_22R_22R
R53 = RES0402: signal model: R_0603_0_R0402_DISCRETE_22R_22R
R56 R57 = RES0402: signal model: R_0603_0_R0402_DISCRETE_22_22
R65 R82 = RES0402: signal model: DEFAUL
R66 = RES0402: signal model: R_R0402_22/NC_22/NC
R83 R91 R96 R97 = RES0603
R92 R95 R157 = RES0805
R109 R110 R210 = RES1206: Tolerance: #TOL; User Part Number: HAMP
R174 R177 R178 R181 = RES0402: signal model: RES0402_R0402_10R_1%_10R_1%
S1 S2 = KEY-2PIN
T1-T10 T17-T24 = TP-D1MM
T11-T16 = MARK
U1 = DC-DC-SY8120B: signal model: CON38_0_FPC-S1A36-05MM_CON38_CON38
U2 = DC-DC-SY8088AAC: signal model: FH81_BGA161_SOCKET_FH8810_FH8810
U3 = TPS793XX: signal model: AXK5S80347YG_SOCKET_ASP80_05MM__AXK5S80347YG_Socket
U4 U5 U12 = DC-DC-SY8088AAC
U6 = NAND FLASH_1
U7 = TSX-3225
U8 = MC146
U9 = NOR FLASH: signal model: RTL8169S_1_QFN32_RTL8201F(E)-(V_RTL8201F(E)-(VC)-CG
U10 = NAND FLASH
U11 = TPS793XX
U13 = SGM4871
U14 = FH8852v200_1
U15 = CON2X4-254MM: User Part Number: HAMP; Tolerance: #TOL
U16 = SY8703_1
U18 = CON2X10-254MM
U19 = AZ6208BM: Tolerance: #TOL; User Part Number: HAMP
U22 = SGM809
U23 = H1102NLT
U26 U27 = HR8833

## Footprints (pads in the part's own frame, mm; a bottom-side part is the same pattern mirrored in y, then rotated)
BAT-22_8-10
  round 0.864 hole 1.118 unplated: (-3.75,0)
  round 1.092 hole 1.346 unplated: (3.75,0)
  rect 5.08x2.794 smd: 1(7.92,0) 2(-8.06,0)
C0201
  rect 0.279x0.432 smd: 1(-0.267,0) 2(0.267,0)
C220D120
  round 5.588 hole 3.048: 1(0,0)
C0402
  custom 0.15x0.15 smd: 1(-0.508,0) 2(0.508,0)
C0603
  rect 0.889x0.813 smd: 1(-0.762,0) 2(0.762,0)
C0805
  rect 1.27x1.397 smd: 1(-0.953,0) 2(0.953,0)
C1206
  rect 1.397x1.6 smd: 1(-1.397,0) 2(1.397,0)
CRSTALY_3225
  rect 1.27x1.016 smd: 1(-1.1,-0.875) 2(1.1,-0.875) 3(1.1,0.875) 4(-1.1,0.875)
D0402
  rect 0.635x0.508 smd: A(-0.508,0) K(0.508,0)
DC-3
  oval 3.302x1.397 hole 2.54x0.635: 1(0,0) 2(0,-6)
  oval 1.397x3.302 hole 0.635x2.54: 3(4.8,-2.5)
DE10MM-H16
  rect 1.524x1.524 hole 1.016: 1(-2.515,0)
  round 1.524 hole 1.016: 2(2.515,0)
DIP4X2_254MM
  rect 1.524x1.524 hole 1.016: 1(0,0)
  round 1.524 hole 1.016: 2(0,-2.54) 3(2.54,0) 4(2.54,-2.54) 5(5.08,0) 6(5.08,-2.54) 7(7.62,0) 8(7.62,-2.54)
DIP10X2_254MM
  rect 1.524x1.524 hole 1.016: 1(0,0)
  round 1.524 hole 1.016: 2(2.54,0) 3(0,-2.54) 4(2.54,-2.54) 5(0,-5.08) 6(2.54,-5.08) 7(0,-7.62) 8(2.54,-7.62) 9(0,-10.16) 10(2.54,-10.16) 11(0,-12.7) 12(2.54,-12.7) 13(0,-15.24) 14(2.54,-15.24) 15(0,-17.78) 16(2.54,-17.78) 17(0,-20.32) 18(2.54,-20.32) 19(0,-22.86) 20(2.54,-22.86)
DO-214AA
  rect 1.702x2.413 smd: A(-2.05,0) K(2.05,0)
DO-214AC
  rect 1.524x1.803 smd: A(-1.85,0) K(1.85,0)
DO-214AC-IN5819
  rect 1.575x2.235 smd: A(-2.11,0) K(2.11,0)
GMI6027P-2C
  rect 1.524x1.524 hole 1.016: 1(-1.27,-1)
  round 1.524 hole 1.016: 2(1.27,-1)
HEADER2_125MM_SMD
  rect 0.61x2.337 smd: 1(-0.625,0.381) 2(0.625,0.381)
  rect 1.905x2.616 smd: CG1(-3.125,2.11) CG2(3.125,2.11)
HEADER4_125MM
  rect 0.914x0.914 hole 0.61: 1(0,0)
  round 0.914 hole 0.61: 2(0,-1.25) 3(0,-2.5) 4(0,-3.75)
HEADER4_125MM_SMD
  rect 0.61x2.337 smd: 1(-1.875,0.381) 2(-0.625,0.381) 3(0.625,0.381) 4(1.875,0.381)
  rect 1.905x2.616 smd: CG1(-4.375,2.11) CG2(4.375,2.11)
HEADER20X2_1MM_SMD
  round 1.524 hole 1.016: (0,11.622) (1.588,-11.623)
  oval 2.388x0.635 smd: 1(-3.53,9.5) 2(3.53,9.5) 3(-3.53,8.5) 4(3.53,8.5) 5(-3.53,7.5) 6(3.53,7.5) 7(-3.53,6.5) 8(3.53,6.5) 9(-3.53,5.5) 10(3.53,5.5) 11(-3.53,4.5) 12(3.53,4.5) 13(-3.53,3.5) 14(3.53,3.5) 17(-3.53,1.5) 18(3.53,1.5) 19(-3.53,0.5) 20(3.53,0.5) 21(-3.53,-0.5) 22(3.53,-0.5) 23(-3.53,-1.5) 24(3.53,-1.5) 25(-3.53,-2.5) 26(3.53,-2.5) 27(-3.53,-3.5) 28(3.53,-3.5) 29(-3.53,-4.5) 30(3.53,-4.5) 31(-3.53,-5.5) 32(3.53,-5.5) 33(-3.53,-6.5) 34(3.53,-6.5) 35(-3.53,-7.5) 36(3.53,-7.5) 37(-3.53,-8.5) 38(3.53,-8.5) 39(-3.53,-9.5) 40(3.53,-9.5)
KEY_2PIN
  round 2.032 hole 1.27: 1(0,3.3) 2(0,-3.3)
L3X3H15
  rect 1.219x3.2 smd: 1(-1.1,0) 2(1.1,0)
L4X4H3
  rect 1.118x3.708 smd: 1(-1.5,0) 2(1.5,0)
LED0603
  rect 0.813x0.813 smd: A(-0.756,0) K(0.756,0)
MC-146
  rect 1.27x0.61 smd: 1(-3.35,-0.45) 2(2.95,-0.45) 3(2.95,0.45) 4(-3.35,0.45)
PHONE_JACK
  round 1.27 hole 1.27 unplated: (-5,5) (-5,2.5) (0,-2.5) (5,5) (5,2.5)
  rect 2.032x2.032 hole 1.524: 1(5,-2.5)
  round 2.032 hole 1.524: 2(2.5,-2.5) 3(-2.5,-2.5) 4(-5,-2.5) 5(0,2.5)
PROCONN_SD
  round 1.601 hole 1.6 unplated: (0,0) (24.2,0)
  rect 1.1x1.5 smd: 1(21.48,24.3) 2(18.98,24.3) 3(16.48,24.3) 4(14.83,24.3) 5(13.18,24.3) 6(11.48,24.3) 7(8.98,24.3) 8(6.48,24.3) 9(4.05,24.3) 10(2.35,24.3) 11(-1,24.3)
  rect 1.676x2.464 smd: 15(-1.6,2.1) 16(26.7,2.1)
PS_3PIN-7MM
  oval 6.35x2.286 hole 5.588x1.524: 1(0,7.1) 2(0,0) 3(0,-7.1)
QFN16_HR8833
  oval 0.914x0.305 smd: 1(-1.95,0.975) 2(-1.95,0.325) 3(-1.95,-0.325) 4(-1.95,-0.975) 9(1.95,-0.975) 10(1.95,-0.325) 11(1.95,0.325) 12(1.95,0.975)
  oval 0.305x0.914 smd: 5(-0.975,-1.95) 6(-0.325,-1.95) 7(0.325,-1.95) 8(0.975,-1.95) 13(0.975,1.95) 14(0.325,1.95) 15(-0.325,1.95) 16(-0.975,1.95)
  rect 2.413x2.413 smd: 17(0,0)
QFN88_HL_SOCKET
  round 4.521 hole 2.413: (-11,11) (-11,-11) (11,11) (11,-11)
  round 1.651 hole 1.651 unplated: (-8.5,8.5) (-8.5,-8.5) (8.5,8.5) (8.5,-8.5)
  oval 0.914x0.178 smd: 1(-4.5,3.675) 2(-4.5,3.325) 3(-4.5,2.975) 4(-4.5,2.625) 5(-4.5,2.275) 6(-4.5,1.925) 7(-4.5,1.575) 8(-4.5,1.225) 9(-4.5,0.875) 10(-4.5,0.525) 11(-4.5,0.175) 12(-4.5,-0.175) 13(-4.5,-0.525) 14(-4.5,-0.875) 15(-4.5,-1.225) 16(-4.5,-1.575) 17(-4.5,-1.925) 18(-4.5,-2.275) 19(-4.5,-2.625) 20(-4.5,-2.975) 21(-4.5,-3.325) 22(-4.5,-3.675) 45(4.5,-3.675) 46(4.5,-3.325) 47(4.5,-2.975) 48(4.5,-2.625) 49(4.5,-2.275) 50(4.5,-1.925) 51(4.5,-1.575) 52(4.5,-1.225) 53(4.5,-0.875) 54(4.5,-0.525) 55(4.5,-0.175) 56(4.5,0.175) 57(4.5,0.525) 58(4.5,0.875) 59(4.5,1.225) 60(4.5,1.575) 61(4.5,1.925) 62(4.5,2.275) 63(4.5,2.625) 64(4.5,2.975) 65(4.5,3.325) 66(4.5,3.675)
  oval 0.178x0.914 smd: 23(-3.675,-4.5) 24(-3.325,-4.5) 25(-2.975,-4.5) 26(-2.625,-4.5) 27(-2.275,-4.5) 28(-1.925,-4.5) 29(-1.575,-4.5) 30(-1.225,-4.5) 31(-0.875,-4.5) 32(-0.525,-4.5) 33(-0.175,-4.5) 34(0.175,-4.5) 35(0.525,-4.5) 36(0.875,-4.5) 37(1.225,-4.5) 38(1.575,-4.5) 39(1.925,-4.5) 40(2.275,-4.5) 41(2.625,-4.5) 42(2.975,-4.5) 43(3.325,-4.5) 44(3.675,-4.5) 67(3.675,4.5) 68(3.325,4.5) 69(2.975,4.5) 70(2.625,4.5) 71(2.275,4.5) 72(1.925,4.5) 73(1.575,4.5) 74(1.225,4.5) 75(0.875,4.5) 76(0.525,4.5) 77(0.175,4.5) 78(-0.175,4.5) 79(-0.525,4.5) 80(-0.875,4.5) 81(-1.225,4.5) 82(-1.575,4.5) 83(-1.925,4.5) 84(-2.275,4.5) 85(-2.625,4.5) 86(-2.975,4.5) 87(-3.325,4.5) 88(-3.675,4.5)
  rect 6.223x6.223 smd: 89(0,0)
R0402
  rect 0.635x0.508 smd: 1(-0.508,0) 2(0.508,0)
R0603
  rect 0.762x0.762 smd: 1(-0.762,0) 2(0.762,0)
R0805
  rect 1.016x1.143 smd: 1(-1.016,0) 2(1.016,0)
R1206
  rect 1.397x1.651 smd: 1(-1.397,0) 2(1.397,0)
RGL55
  round 1.118 hole 0.711: A(-1.7,0) K(1.7,0)
RJ45_LED-1
  round 3.404 hole 3.404 unplated: (-2.78,2.54) (9.92,2.54)
  rect 1.422x1.422 hole 0.914: 1(0,0)
  round 1.422 hole 0.914: 2(1.02,-1.78) 3(2.04,0) 4(3.06,-1.78) 5(4.08,0) 6(5.1,-1.78) 7(6.12,0) 8(7.14,-1.78)
  round 1.626 hole 1.118: 9(-3.29,-6.64) 10(-1,-6.64) 11(8.14,-6.64) 12(10.43,-6.64)
  round 2.362 hole 1.6: 13(-4.56,-0.89) 14(11.7,-0.89)
SIP2_254MM
  rect 1.524x1.524 hole 1.016: 1(0,0)
  round 1.524 hole 1.016: 2(2.54,0)
SIP3_254MM
  rect 1.651x1.651 hole 1.016: 1(0,0)
  round 1.651 hole 1.016: 2(2.54,0) 3(5.08,0)
SIP4_254MM
  rect 1.651x1.651 hole 1.016: 1(0,0)
  round 1.651 hole 1.016: 2(2.54,0) 3(5.08,0) 4(7.62,0)
SO8_200MIL
  oval 2.007x0.432 smd: 1(-3.75,1.905) 2(-3.75,0.635) 3(-3.75,-0.635) 4(-3.75,-1.905) 5(3.75,-1.905) 6(3.75,-0.635) 7(3.75,0.635) 8(3.75,1.905)
SOD323
  rect 0.914x0.965 smd: A(-1.125,0) K(1.125,0)
SOD-323
  rect 0.635x0.838 smd: A(1.118,0) K(-1.118,0)
SOIC8-SGM4871
  oval 1.803x0.533 smd: 1(-3.1,1.905) 2(-3.1,0.635) 3(-3.1,-0.635) 4(-3.1,-1.905) 5(3.1,-1.905) 6(3.1,-0.635) 7(3.1,0.635) 8(3.1,1.905)
  rect 2.515x3.404 smd: 9(0,0)
SOP8-NANDFLASH
  oval 1.219x0.406 smd: 1(-4,1.905) 2(-4,0.635) 3(-4,-0.635) 4(-4,-1.905) 5(4,-1.905) 6(4,-0.635) 7(4,0.635) 8(4,1.905)
  rect 3.404x4.318 smd: 9(0,0)
SOP8_127-620X500
  oval 2.159x0.61 smd: 1(-2.565,1.905) 2(-2.565,0.635) 3(-2.565,-0.635) 4(-2.565,-1.905) 5(2.565,-1.905) 6(2.565,-0.635) 7(2.565,0.635) 8(2.565,1.905)
SOP8_SPI_SOCKET-267X17
  round 1.016 hole 0.508: 1(-3.56,1.92) 2(-5.48,0.65) 3(-3.56,-0.62) 4(-5.48,-1.89) 5(4.01,-1.89) 6(5.93,-0.62) 7(4.01,0.65) 8(5.93,1.92) 9(-1.27,4.35) 10(-1.27,-4.35)
SOP16_270_50
  oval 0.635x1.778 smd: 1(-4.445,-4.318) 2(-3.175,-4.318) 3(-1.905,-4.318) 4(-0.635,-4.318) 5(0.635,-4.318) 6(1.905,-4.318) 7(3.175,-4.318) 8(4.445,-4.318) 9(4.445,4.318) 10(3.175,4.318) 11(1.905,4.318) 12(0.635,4.318) 13(-0.635,4.318) 14(-1.905,4.318) 15(-3.175,4.318) 16(-4.445,4.318)
SOT23
  rect 0.813x1.016 smd: 1(-0.95,-1.15) 2(0.95,-1.15) 3(0,1.15)
SOT23_2
  rect 0.813x1.016 smd: 1(0.94,1.145) 2(-0.94,1.145) 3(0,-1.055)
SOT23_5
  rect 0.635x1.321 smd: 1(-0.95,-1.35) 2(0,-1.35) 3(0.95,-1.35) 4(0.95,1.35) 5(-0.95,1.35)
SOT23_6
  rect 0.635x1.27 smd: 1(-0.95,-1.275) 2(0,-1.275) 3(0.95,-1.275) 4(0.95,1.275) 5(0,1.275) 6(-0.95,1.275)
SOT_23
  rect 0.813x0.889 smd: 1(0.94,2.007) 2(-0.94,2.007) 3(0,0)
TP30
  round 0.762 smd: 1(0,0)
TSOT23-6
  rect 0.457x1.016 smd: 1(-0.95,-1.375) 2(0,-1.375) 3(0.95,-1.375) 4(0.95,1.375) 5(0,1.375) 6(-0.95,1.375)
USBX1_SMD
  round 1.321 hole 1.321 unplated: (-1.5,-4.96) (3.5,-4.96)
  rect 1.143x2.896 smd: 1(-2.5,0) 2(0,0) 3(2,0) 4(4.5,0)
  rect 2.667x4.902 smd: CG1(-6.625,-3.46) CG2(8.625,-3.46)

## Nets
D0.9V: C61.1 C88.1 C89.1 C90.1 C91.1 C92.1 C93.1 C191.1 JP15.2 JP16.2 T9.1 U14.19(VDDK_3) U14.32(VDDK_4) U14.40(VDDK_2) U14.53(VDDK_0) U14.74(VDDK_5) U14.79(VDDK_1)
D1.8V: D12.A J14.4 JP18.2 R29.1 R30.2 R32.2 R34.1 R35.1 R36.1 R60.2 R97.2 R131.2 R168.2 R169.1 T4.1
D3.3V: C60.1 C96.1 C100.2 C101.1 C148.1 C150.2 C151.1 C160.1 C194.1 C195.2 D6.2(C2) D8.A J12.1 JP13.2 MQ1.2(SOURCE) R28.2 R42.2 R45.2 R47.2 R52.1 R53.1 R54.2 R55.1 R56.2 R57.2 R59.1 R73.2 R81.1 R83.2 R96.2 R122.2 R124.2 R135.2 R136.2 R137.2 R138.2 R140.2 R141.2 R161.2 R164.1 R167.1 T3.1 U6.8(VCC) U9.8(VCC) U10.8(VCC) U15.1 U15.2 U18.1 U18.2
D5.0V: C11.2 C12.2 C17.2 C18.2 C25.2 C26.2 C34.2 C35.2 C64.2 C65.2 C99.1 C107.2 C109.2 JP8.2 MQ3.2(SOURCE) R7.1 R10.1 R15.1 R18.1 R21.1 R24.1 R44.1 R50.1 R86.1 R91.2 R105.1 R157.1 R159.2 R210.1 T1.1 U2.4(VIN) U3.1(VIN) U4.4(VIN) U5.4(VIN) U11.1(VIN) U12.4(VIN)
D12V: C2.1 C4.1 C5.1 C105.1 C106.1 C152.1 C153.1 D1.K D26.K R1.2 R2.1 R109.1 R110.1 U1.5(VIN) U16.5(IN) U19.1(VCC)
GND: BT1.2(-) C2.2 C3.2 C4.2 C5.2 C6.2 C7.2 C9.2 C10.1 C11.1 C12.1 C14.2 C15.2 C16.2 C17.1 C18.1 C19.2 C20.1 C21.2 C22.2 C23.1 C24.2 C25.1 C26.1 C28.2 C29.2 C30.2 C31.1 C32.2 C33.2 C34.1 C35.1 C37.2 C38.2 C39.2 C40.2 C41.1 C42.2 C43.2 C44.2 C45.1 C46.1 C47.1 C48.2 C49.2 C50.1 C51.2 C52.1 C53.2 C54.2 C55.2 C57.2 C58.2 C59.1 C60.2 C61.2 C62.2 C63.1 C64.1 C65.1 C67.2 C68.2 C69.2 C70.1 C71.1 C72.1 C74.2 C75.2 C77.1 C78.1 C79.1 C80.1 C81.1 C82.1 C83.1 C85.1 C87.2 C88.2 C89.2 C90.2 C91.2 C92.2 C93.2 C97.2 C98.2 C100.1 C101.2 C102.2 C103.2 C104.2 C105.2 C106.2 C107.1 C108.2 C109.1 C110.2 C111.2 C112.2 C113.2 C114.2 C115.2 C116.2 C117.2 C118.1 C119.2 C120.2 C121.2 C122.2 C123.2 C124.2 C125.2 C135.2 C147.2 C148.2 C149.2 C150.1 C151.2 C152.2 C153.2 C158.2 C159.2 C160.2 C161.2 C162.2 C163.2 C164.2 C165.2 C166.1 C167.2 C177.2 C178.2 C181.1 C183.1 C184.1 C185.1 C186.2 C188.2 C190.1 C191.2 C194.2 C195.1 C196.1 CN1.5 CN5.5 D2.A D3.K D7.K D8.K D9.A D10.A D13.K D14.A D15.A D16.A D17.A D18.K D19.A D21.K D22.K D23.A D24.K D25.A J1.2 J1.3 J2.3 J3.1 J3.4 J3.6 J3.7 J3.10 J3.12 J3.13 J3.18 J3.20 J3.21 J3.24 J3.26 J3.27 J3.30 J3.32 J3.33 J3.37 J3.38 J4.5(GND2) J4.8(GND1) J4.15(GND3) J4.16(GND4) J5.CG1 J5.CG2 J6.2 J7.CG1 J7.CG2 J12.2 J13.2 J13.CG1 J13.CG2 J14.3 J15.CG1 J15.CG2 J17.13(SOLDER1) J17.14(SOLDER2) J19.CG1 J19.CG2 J20.CG1 J20.CG2 J21.4(GND) J21.CG1 J21.CG2 JP5.1 JP5.2 JP6.1 JP6.2 JP20.3 Q1.2(E) Q3.2(E) Q4.2(E) R4.1 R5.1 R8.1 R9.1 R11.1 R16.1 R17.1 R19.2 R22.2 R25.1 R26.1 R31.2 R38.1 R43.2 R46.2 R48.2 R49.2 R74.1 R80.2 R84.2 R87.1 R88.1 R104.2 R106.1 R132.1 R134.2 R139.2 R142.2 R173.1 R176.1 R179.1 RF2.1 RR2.1 RR3.1 S1.1 S2.1 T2.1 T5.1 T6.1 T8.1 T10.1 T11.1 T12.1 T13.1 T14.1 T15.1 T16.1 T18.1 U1.2(GND) U2.2(GND) U3.2(GND) U4.2(GND) U5.2(GND) U6.4(GND) U6.9(PAD1) U6.10(PAD2) U7.2 U7.4 U9.4(GND) U10.4(GND) U10.9(PAD) U11.2(GND) U12.2(GND) U13.7(GND) U13.9(PAD) U14.37(GNDA_PLL) U14.89(GND_PAD) U15.3 U15.4 U16.2(GND) U16.3(TM) U18.4 U18.6 U18.8 U18.10 U18.12 U18.14 U18.16 U18.18 U18.20 U19.3(GND#3) U19.7(GND#7) U22.1(GND) U26.1(AISEN) U26.4(BISEN) U26.11(GND) U26.17(PAD) U27.1(AISEN) U27.4(BISEN) U27.11(GND) U27.17(PAD)
VBUS: D17.K J21.1(VCC) R160.2
AC_MICBIAS: C114.1 C135.1 R107.2 U14.18(AC_MICBIAS)
AC_MICIP: C56.2 JP17.2
AC_OUTL: JP23.2 U14.15(AC_OUTL)
AMP+: R94.1 R98.2 U13.5(VO1)
AMP-: R90.1 U13.8(VO2)
ARM_DBGRQ: R142.1 U18.17
ARM_JTAG_TCK: JP9.3 R138.1 U18.9
ARM_JTAG_TDI: JP7.3 R136.1 U18.5
ARM_JTAG_TDO: JP12.3 R140.1 U18.13
ARM_JTAG_TMS: JP10.3 R137.1 U18.7
ARM_JTAG_TRSTN: JP11.3 R135.1 R143.1 U18.3
BOOT_MODE: JP1.2 U14.77(BOOT_MODE/GPIO30)
BOOT_SEL0: JP3.2 U14.75(BOOT_SEL0/GPIO32)
BOOT_SEL1: JP2.2 U14.76(BOOT_SEL1/GPIO31)
CDS1: JP29.2 R129.2
CDS2: JP30.2 R130.1
CH_UART1_RX: JP22.2 U14.58(UART1_RX)
CIS_CLK: C52.2 J3.40 R33.1
CIS_RSTN: J3.14 U14.8(SENSOR_RSTN/GPIO13)
CIS_SCL: J3.36 R34.2 U14.11(I2C0_SCL/GPIO35)
CIS_SDA: J3.34 R35.2 U14.10(I2C0_SDA/GPIO36)
CLK_IN: R39.2 U14.41(CLK_IN)
CLK_OUT: R40.1 R41.2 U14.42(CLK_OUT)
DDR_D1.8V: C27.1 C28.1 C29.1 C30.1 JP19.1 L3.2 R14.2 T7.1
DDR_D1.35V: C66.1 C67.1 C68.1 C69.1 JP19.3 L5.2 R85.2 T17.1
DDR_IO: C48.1 C57.1 C58.1 C98.1 C116.1 C117.1 C120.1 C121.1 JP19.2 U14.33(VDDIO_DDR_18_0) U14.36(VDDIO_DDR_18_1)
E0_CT1: C165.1 U23.2(CT1)
E0_CT2: C167.1 U23.7(CT2)
EN1: C32.1 D4.K R13.1 R19.1 R20.1 R89.1
EN2: C62.1 D11.K R12.1 R84.1
EN3: C33.1 D5.K R22.1 R27.1
EPHY_RXN: C155.2 D32.K R181.2 U14.67(EPHY_RXN)
EPHY_RXP: C155.1 D32.A R178.2 U14.68(EPHY_RXP)
EPHY_TXN: C154.2 D20.K R177.2 U14.69(EPHY_TXN)
EPHY_TXP: C154.1 D20.A R174.2 U14.70(EPHY_TXP)
ETH_ACT: D19.K J17.12(LEDY+) JP4.1
ETH_STA: D23.K J17.10(LEDR+) U14.81(GPIO_29)
GPIO_0: JP11.2 U14.47(GPIO_0)
GPIO_1: JP12.2 U14.48(GPIO_1)
GPIO_2: JP7.2 U14.49(GPIO_2)
GPIO_3: JP9.2 U14.50(GPIO_3)
GPIO_4: JP10.2 U14.51(GPIO_4)
GPIO_28: JP4.2 U14.80(GPIO_28)
GPIO_RESET: R166.2 U14.24(PWM_1)
HOLD: R54.1 R58.1 U6.7(IO3/HOLD) U9.7(/HOLD/IO3) U10.7(IO3/HOLD)
IR_LED_IN: J13.1 R133.2
IRCUT_OFF: JP10.1 R144.2
IRCUT_ON: R145.2 U14.25(PWM_0)
IRCUT_OUT_OFF: J15.1 U19.4(OUT A)
IRCUT_OUT_ON: J15.2 U19.2(OUT B)
IRLED+: J7.1 R99.2
IRLED-: J7.2 R111.2
JTAG_RTCK: R139.1 U18.11
JTAG_SRSTN: R141.1 R143.2 U18.15
LDO_MICBIAS: C110.1 C111.1 C112.1 R103.2 U11.5(VOUT)
MIPI_CKN: J3.19 T24.1 U14.5(MIPI_CKN)
MIPI_CKP: J3.17 T23.1 U14.6(MIPI_CKP)
MIPI_D5.0V: J3.35 R50.2
MIPI_DN0: J3.5 T20.1 U14.1(MIPI_DN0)
MIPI_DN1: J3.11 T22.1 U14.4(MIPI_DN1)
MIPI_DP0: J3.3 T19.1 U14.2(MIPI_DP0)
MIPI_DP1: J3.9 T21.1 U14.3(MIPI_DP1)
MOTO_OUT_2: R150.1 U26.16(AOUT1)
MOTO_OUT_3: J19.2 U26.2(AOUT2)
MOTO_OUT_4: R151.1 U26.5(BOUT1)
MOTO_OUT_5: J19.4 U26.3(BOUT2)
MOTO_OUT_6: R152.1 U27.16(AOUT1)
MOTO_OUT_7: J20.2 U27.2(AOUT2)
MOTO_OUT_8: R153.1 U27.5(BOUT1)
MOTO_OUT_9: J20.4 U27.3(BOUT2)
NAND_CS: JP14.3 R59.2 U6.1(CS) U10.1(CS)
NOR_CS: JP14.1 R52.2 U9.1(/CS)
PHY_RN: J17.6(RX-) U23.9(RX-)
PHY_RP: J17.3(RX+) U23.11(RX+)
PHY_TN: J17.2(TX-) U23.14(TX-)
PHY_TP: J17.1(TX+) U23.16(TX+)
PWM11: JP22.3 R108.1
PWM_2: U14.55(I2C1_SCL) U26.14(AIN1)
PWM_3: U14.54(I2C1_SDA) U26.13(AIN2)
PWM_4: U14.57(UART2_TX) U26.7(BIN1)
PWM_5: U14.56(UART2_RX) U26.8(BIN2)
PWM_6: JP11.1 U27.14(AIN1)
PWM_7: JP12.1 U27.13(AIN2)
PWM_8: JP7.1 U27.7(BIN1)
PWM_9: JP9.1 U27.8(BIN2)
RESETN: C190.2 R172.2 U14.43(RESETN)
RTC_VBAT: C102.1 R37.1 R61.1
RTC_XIN: C79.2 U8.1 U14.45(RTC_XIN)
RTC_XOUT: C81.2 U8.4 U14.46(RTC_XOUT)
SD0_3.3V: C103.1 C104.1 J4.6(VCC) MQ1.3(DRAIN) R64.1 R65.1 R66.1 R67.1 R74.2 R82.1
SD0_CD: R75.1 R77.1 U14.88(SD0_CD)
SD0_CLK: C178.1 R72.1 R204.1
SD0_CMD: R79.1 U14.86(SD0_CMD_RSP)
SD0_DATA_0: R68.1 U14.85(SD0_DATA_0)
SD0_DATA_1: R69.1 U14.84(SD0_DATA_1)
SD0_DATA_2: R70.1 U14.83(SD0_DATA_2)
SD0_DATA_3: R71.1 U14.82(SD0_DATA_3)
SD0_EN: JP4.3 R78.1 R80.1
SPI0_CLK: C177.1 R56.1 R203.1 U6.6(CLK) U9.6(CLK) U10.6(CLK)
SPI0_CSN_0: JP14.2 U14.27(SSI0_CSN_0)
SPI0_D_2: R51.1 U14.30(SSI0_D2)
SPI0_D_3: R58.2 U14.31(SSI0_D3)
SPI0_RXD: R53.2 U6.2(SO/IO1/TXD) U9.2(SO/IO1/TXD) U10.2(SO/IO1/TXD) U14.29(SSI0_RXD)
SPI0_TXD: R57.1 U6.5(IO0/SI/RXD) U9.5(SI/IO0/RXD) U10.5(IO0/SI/RXD) U14.28(SSI0_TXD)
UART0_RX: R122.1 R127.1 U14.22(UART0_RX/GPIO34) U15.7
UART0_TX: R124.1 R125.1 U14.23(UART0_TX/GPIO33) U15.5
UART1_RX: JP22.1 U15.8
UART1_TX: U14.59(UART1_TX) U15.6
USB_DM: R146.1 U14.65(USB_DM)
USB_DP: R147.1 U14.64(USB_DP)
USB_PWREN: R162.1 U14.60(USB_PWREN)
USB_VBUS: C196.2 R158.2 U14.62(USB_VBUS)
USBN: D13.A J21.2(D-) R146.2
USBP: D14.K J21.3(D+) R147.2
VM: C181.2 C182.2 C183.2 C184.2 C185.2 C187.2 R207.1 R208.1 R209.1 R210.2 R211.1 U26.10(VM) U27.10(VM)
WP: R51.2 R55.2 U6.3(WP/IO2) U9.3(/WP/IO2) U10.3(WP/IO2)
XAIN0_SADC: C97.1 J14.1 JP29.1 JP30.1 U14.12(SADC_XAIN0/GPIO26)
XAIN1_SADC: C44.1 J14.2 JP20.1 U14.13(SADC_XAIN1/GPIO27)
N00509: C149.1 D12.K R129.1 R132.2
N00760: J4.9(DATA0) R67.2 R68.2
N00772: J4.10(DATA1) R66.2 R69.2
N00784: J4.1(DATA2) R65.2 R70.2
N00796: J4.2(DATA3) R64.2 R71.2
N00808: J4.7(CLK) R72.2
N00832: J4.4(CARD) R77.2 R81.2
N00844: J4.3(CMD) R79.2 R82.2
N04317: R144.1 U19.8(IN A)
N04321: R145.1 U19.5(IN B)
N04628: D9.K J12.4 R127.2
N04632: D10.K J12.3 R125.2
N05813: C146.2 RF1.1 RF2.2
N05817: C147.1 CN5.1 RF1.2
N06013: R164.2 R165.1 S1.2
N06017: C161.1 R165.2 R166.1
N06505: C163.1 C164.1 R168.1 R171.2 R172.1 S2.2
N06945: R170.2 R171.1 R173.2
N06949: R170.1 U22.2(/RESET)
N07170: C162.1 R167.2 R169.2 U22.3(VCC)
N07819: C158.1 C159.1 MQ3.3(DRAIN) R157.2 R158.1 R160.1
N08066: C3.1 D2.K J1.1 J2.1
N08150: D1.A J2.2
N08491: C99.2 MQ3.1(GATE) R101.2 R159.1
N08611: Q4.1(B) R163.2
N08717: R161.1 R162.2 R163.1
N08811: Q1.3(C) R75.2 R76.1
N09072: D3.A R1.1
N09124: C96.2 MQ1.1(GATE) R73.1 R76.2
N09603: C1.1 U1.1(BS)
N09840: C1.2 L1.1 U1.6(SW)
N09899: C6.1 C7.1 C8.1 C9.1 JP8.1 L1.2 R3.2
N09903: C8.2 R3.1 R5.2 U1.3(FB)
N11558: C20.2 R7.2 R8.2 R12.2 U2.1(EN)
N12312: L2.1 U2.3(LX)
N12324: C13.1 C14.1 C15.1 C16.1 JP13.1 L2.2 R6.2
N12328: C13.2 R6.1 R9.2 U2.5(FB)
N12968: Q3.1(B) R133.1 R134.1
N13141: Q3.3(C) R130.2 R131.1
N15061: C27.2 R14.1 R16.2 U4.5(FB)
N15235: C31.2 R15.2 R17.2 R20.2 U4.1(EN)
N15383: L3.1 U4.3(LX)
N17654: C36.2 R23.1 R26.2 U5.5(FB)
N17828: C41.2 R24.2 R25.2 R27.2 U5.1(EN)
N17960: L4.1 U5.3(LX)
N17964: C36.1 C37.1 C38.1 C39.1 C40.1 JP15.1 JP16.1 L4.2 R23.2
N20335: C23.2 R10.2 R11.2 R13.2 U3.3(EN)
N20515: C19.1 C21.1 C22.1 JP18.1 U3.5(VOUT)
N28498: C10.2 R2.2 R4.2 U1.4(EN)
N36801: C24.1 U3.4(NR)
N41621: D4.A R18.2
N41625: D5.A R21.2
N052210: Q1.1(B) R78.2
N58665: C113.1 R102.2 R103.1 R107.1
N58697: C108.1 J6.1 JP17.1 R102.1
N58961: C118.2 R105.2 R106.2 U11.3(EN)
N59213: C119.1 CN1.1 JP17.3
N59225: C115.1 U11.4(NR)
N071991: Q4.3(C) R101.1
N16425733: J17.9(LEDR-) R179.2
N16425793: J17.11(LEDY-) R176.2
N16425805: C166.2 R92.1 R95.1
N16425817: D24.A R181.1 U23.8(RD-)
N16425841: D22.A R178.1 U23.6(RD+)
N16425857: D21.A R177.1 U23.3(TD-)
N16425869: D18.A R174.1 U23.1(TD+)
N16426003: D15.K R92.2 U23.15(CT4)
N16426121: D16.K R95.2 U23.10(CT3)
N16457705: C82.2 C83.2 C85.2 R83.1 U14.21(VDDIO_18OD33_2) U14.52(VDDIO_18OD33_0) U14.78(VDDIO_18OD33_1)
N16486091: JP3.3 R48.1
N16486095: JP3.1 R47.1
N16486099: JP2.3 R46.1
N16486103: JP2.1 R45.1
N16486107: JP1.3 R43.1
N16486111: JP1.1 R42.1
N16486523: R49.1 U14.72(EPHY_REXT)
N16520538: D6.3(A) R61.2
N16520613: BT1.1(+) D6.1(C1)
N16568818: C187.1 U26.9(VCP)
N16568861: C186.1 U26.12(VINT)
N16569733: R209.2 U26.6(NFAULT)
N16569735: R211.2 U26.15(NSLEEP)
N16571206: C182.1 U27.9(VCP)
N16571226: C188.1 U27.12(VINT)
N16571270: R208.2 U27.6(NFAULT)
N16571274: R207.2 U27.15(NSLEEP)
N16589672: R203.2 U14.26(SSI0_CLK)
N16609598: R204.2 U14.87(SD0_CLK)
N16674187: J19.1 R150.2
N16674222: J19.3 R151.2
N16674257: J20.1 R152.2
N16674292: J20.3 R153.2
N16750026: C71.2 C72.2 R91.1 U13.6(V+)
N16750096: D7.A J5.1 R90.2
N16750100: D25.K J5.2 R94.2
N16750228: C59.2 U13.2(BYPASS) U13.3(+IN)
N16750268: R63.2 U13.1(SHDN)
N16750308: R60.1 R62.2 R63.1
N16750370: R93.2 R98.1 U13.4(-IN)
N16750378: C73.2 R93.1
N16750486: C146.1 JP23.3
N16751027: C73.1 JP23.1
N16751673: JP20.2 R62.1
N16764243: C87.1 R104.1 R108.2 U16.4(EN)
N16764537: C86.1 C94.1 C95.1 R99.1 R109.2 R110.2 U16.6(SEN)
N16764551: D26.A L6.1 U16.1(LX)
N16764573: C86.2 C94.2 C95.2 L6.2 R111.1
N16771686: D11.A R44.2
N16778150: C66.2 R85.1 R88.2 U12.5(FB)
N16778213: C70.2 R86.2 R87.2 R89.2 U12.1(EN)
N16778255: L5.1 U12.3(LX)
N16785770: R38.2 U14.7(MIPI_REXT)
N16786493: R33.2 U14.9(SENSOR_CLK/GPIO12)
N16786550: C47.2 C63.2 R36.2 U14.20(VDDIO_18)
N16786676: C45.2 C50.2 R29.2 U14.39(VDDA18_PLL)
N16786698: C46.2 U14.38(VDDA09_PLL)
N16789313: R31.1 U14.66(USB_REXT)
N16794051: C49.1 C51.1 R30.1 U14.61(VDDIO_18/VDDA18_USB)
N16794071: C42.1 C43.1 R28.1 U14.63(VDDA33_USB)
N16795142: C74.1 C75.1 U14.16(AC_VMID)
N16795478: C77.2 R37.2 U14.44(VDDA33_RTC)
N16795922: C78.2 R39.1 R40.2 U7.1
N16795926: C80.2 R41.1 U7.3
N16800878: C53.1 C54.1 R32.1 U14.14(VDDA18_AC/MIPI/SADC)
N16800900: C55.1 C56.1 U14.17(AC_MICIP)
N16803827: RR3.2 U14.34(DDR_ZQ)
N16803833: RR2.2 U14.35(DDR_CAL)
N16837752: C124.1 C125.1 R97.1 U14.73(VDDIO_18/VDDA18_EPHY)
N16837764: C122.1 C123.1 R96.1 U14.71(VDDA33_EPHY)

Pads without a net: CN1 2 3 4; CN5 2 3 4; J3 2 8 22 23 25 28 29 31 39; J4 11; J17 4 5 7 8; U8 2 3; U18 19; U19 6; U23 4 5 12 13

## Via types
v1: diameter 0.457, hole 0.254, TOP to BOTTOM, 1656 vias
v2: diameter 0.61, hole 0.305, TOP to BOTTOM, 7 vias

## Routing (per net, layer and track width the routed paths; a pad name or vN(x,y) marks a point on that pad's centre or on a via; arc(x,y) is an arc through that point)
D0.9V: length 14.9
  TOP w0.178: v1(57.86,37.41) 57.89,37.38 U14.32 ; v1(62.03,40.13) 62.04,40.15 U14.53 ; U14.79 57.89,44.64 v1(57.86,44.6) ; U14.40 60.7,37.35 v1(60.81,37.47) ; U14.74 v1(59.65,44.62) ; U14.19 54.65,38.4 v1(54.71,38.46)
  TOP w0.381: T9.1 JP16.2
  BOTTOM w0.381: v1(54.71,38.46) 54.74,38.48 C88.1 C89.1 ; v1(57.86,44.6) 57.71,44.45 C90.1 C93.1 ; C91.1 60.96,37.62 v1(60.81,37.47) ; v1(62.03,40.13) 61.98,40.18 C92.1 ; C61.1 59.47,44.45 v1(59.65,44.62) ; v1(57.86,37.41) 57.78,37.34 C191.1
D1.8V: length 224.8
  TOP w0.305: v1(48.69,23.11) 27.2,23.11 23.39,19.3 21.97,19.3 v1(21.84,19.43)
  TOP w0.381: v1(114.88,19.1) 114.43,19.56 v1(106.55,19.56) 106.05,20.07 102.61,20.07 95.76,26.92 ; 95.76,26.92 95.76,26.92 v1(89.41,26.92) ; 95.76,26.92 95.76,44.07 99.19,47.5 JP18.2 T4.1 ; v2(41.78,52.32) 39.95,50.5 18.24,50.5 16.43,52.3 D12.A 16.43,69.55 v1(8.76,77.22) 8.76,86.36 J14.4
  TOP w0.508: v1(47.14,42.7) 47.12,42.67 ; 47.12,42.67 45.72,42.67 44.96,41.91 v1(44.96,38.86) 44.96,38.13 46.79,36.3 48.62,36.3 49.17,35.74 51.13,35.74 v1(52.32,34.54) ; 47.12,42.67 47.12,41.91 v1(46.99,41.78)
  VCC w0.381: v1(89.41,26.92) 72.26,26.92 71.88,26.54 67.89,26.54 63.32,31.11 v1(62.99,31.11)
  BOTTOM w0.305: v1(71.07,44.32) 70.31,43.56 R30.2 ; R60.2 v1(21.84,19.43) ; v1(114.88,19.1) R168.2
  BOTTOM w0.381: v1(106.55,19.56) 107.31,18.8 R169.1 ; 53.85,29.44 56.36,29.44 58.04,31.11 R29.1 v1(62.99,31.11) ; 53.85,29.44 52.56,29.44 48.64,25.52 48.64,23.16 v1(48.69,23.11) ; 53.85,29.44 53.98,29.57 53.98,33.53 R36.1 53.47,33.78 52.7,34.54 v1(52.32,34.54) ; v1(47.14,42.7) 47.22,42.77 47.85,42.77 R35.1 ; R32.2 v1(44.96,38.86) ; R34.1 v1(46.99,41.78) ; v1(59.05,51.51) R97.2
  BOTTOM w0.508: 8,77.22 v1(8.76,77.22)
D3.3V: length 246.5
  TOP w0.305: v1(82.17,12.06) 82.14,12.04 80.95,12.04 v1(80.8,12.19) ; v1(70.23,12.95) 70.74,13.46 U9.8
  TOP w0.381: v1(70.23,12.95) 67.94,12.95 v1(67.56,13.34)
  TOP w0.762: v2(109.45,4.17) 107.98,4.17 101.08,11.06 U6.8 100.54,13.48 v1(100.21,13.82) v1(99.7,13.82) v1(99.19,13.82) 99.17,13.84 95,13.84 94.23,14.61 v1(83.82,14.61) 83.44,14.99 v1(83.44,16.76) v1(83.44,17.78)
  VCC w0.254: v1(33.4,62.46) 32.21,62.46 31.37,61.62 31.37,57.25
  VCC w0.305: U15.1 U15.2
  VCC w0.381: v1(83.44,17.78) 83.03,18.18 70.89,18.18 v1(69.98,17.27) ; v2(109.45,4.17) 119.61,4.17 119.76,4.32 ; v1(127.13,7.75) 129.67,7.75 v2(130.18,7.24) 130.3,7.11 J12.1 128.8,2.18 120.5,2.18 U15.1
  VCC w0.635: 103.91,18.25 104.13,18.03 v1(108.97,18.03) 109.35,18.03 v1(110.74,16.64) ; 107.72,34.92 92.96,34.92 90.49,32.45 v2(87,32.45)
  VCC w1.016: 123.47,49.96 122.76,50.67 113.08,50.67 107.72,45.31 107.72,25.68 103.91,21.87 103.91,17.42 100.3,13.82 v1(100.21,13.82) v1(99.7,13.82) v1(99.19,13.82)
  BOTTOM w0.305: R136.2 v1(145.03,70.61) ; v1(80.8,12.19) 80.67,12.06 71.12,12.06 v1(70.23,12.95) 69.6,12.32 69.22,12.32 ; v1(25.02,56.26) 24.89,56.13 R42.2 ; C60.1 100.66,11.18 U6.8 ; U15.1 120.27,3.43 C194.1 C195.2 120.4,4.83 U15.2 ; U10.8 v1(69.98,17.27) 69.34,17.27 69.22,17.4 ; R59.1 v1(83.44,17.78) ; C150.2 C151.1 ; C150.2 146.81,74.93 v1(145.03,73.15) R135.2 ; C150.2 149.61,75.06 U18.1 U18.2 ; J12.1 130.18,3.81 130.18,5.21 ; R47.2 37.34,56.13 v1(37.21,56.26) ; R161.2 v1(100.2,66.67) ; R137.2 v1(145.03,68.07) ; R53.1 v1(83.44,16.76) ; R122.2 v1(127.13,7.75) R124.2 ; v1(33.4,62.46) 33.05,62.1 R81.1 ; v1(83.82,14.61) R55.1 82.93,14.22 82.93,13.08 R52.1 82.55,12.45 v1(82.17,12.06) ; C96.1 49.91,62.36 v1(49.4,61.85) ; R138.2 v1(145.03,65.53) ; R140.2 145.16,60.45 v1(145.03,60.58) ; R45.2 v1(31.24,56.77) ; R54.2 R56.2 R57.2 ; v1(110.74,16.64) 111.12,16.26 C160.1 R164.1 ; R141.2 145.16,57.91 v1(145.03,58.04) ; R28.2 v1(70.1,46.28) ; R167.1 v1(108.97,18.03)
  BOTTOM w0.381: v1(48.64,62.23) R73.2 v1(47.88,63.12) 47.5,63.12 47.42,63.2 MQ1.2 v1(47.09,62.38) ; R57.2 v1(67.56,13.34) ; R96.2 v1(63.37,53.77)
  BOTTOM w0.508: 130.18,5.21 v2(130.18,7.24)
  BOTTOM w0.635: D6.2 v2(87,32.45)
  vias: v1(57.53,52.32) v1(58.04,52.32) v1(99.72,53.21) v1(99.75,52.55) v1(100.23,53.21) v1(100.23,52.53) v1(100.74,53.21) v1(100.71,52.55) v1(123.8,48.72) v1(124.59,48.77) v1(125.22,48.84)
